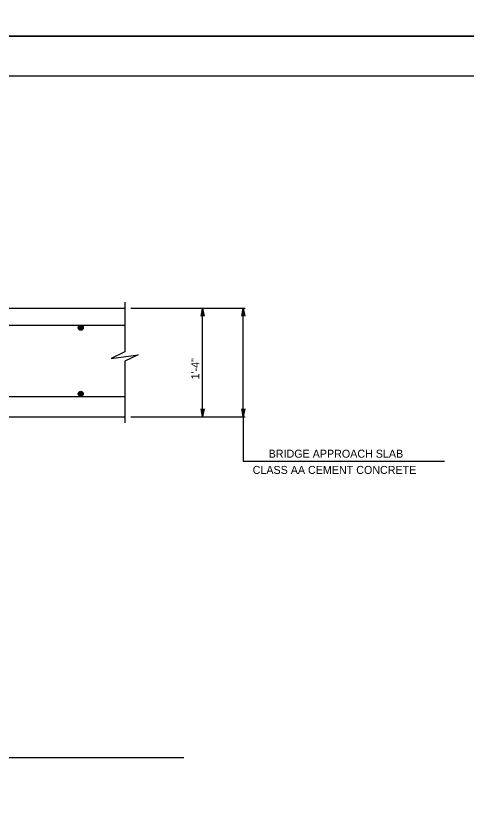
# Model space of a CAD drawing. Extents: x 636530 to 644067, y 294168 to 299122.
# Drawn here: x 639324.5 to 639493.4, y 296844.4 to 297146 of the extents above; entities that cross this region are included whole.
import ezdxf

# ---------------------------------------------------------------- set-up
doc = ezdxf.new("R2010")
doc.units = 0
doc.layers.add('1', color=7, linetype='Continuous')
doc.layers.add('PLT-BNDY', color=7, linetype='Continuous')

msp = doc.modelspace()

# ---------------------------------------------------------------- linework, layer by layer
at = {"layer": '1'}
for p, q in [((639832.78, 297123.48), (639046.78, 297123.48)), ((639217.03, 297036.51), (639365.32, 297036.51)), ((639365.32, 297038.81), (639365.32, 297020.15)), ((639367.53, 297036.51), (639410.31, 297036.51)), ((639394.39, 296995.87), (639394.39, 297036.51)), ((639409.63, 296995.87), (639409.63, 297036.51)), ((639314.79, 297030.16), (639365.32, 297030.16)), ((639365.32, 297016.63), (639365.32, 296993.56)), ((639314.79, 297003.49), (639365.32, 297003.49)), ((639215.69, 296995.87), (639365.32, 296995.87)), ((639367.53, 296995.87), (639410.31, 296995.87)), ((639409.63, 296995.87), (639409.63, 296979.14)), ((639409.63, 296979.14), (639485.02, 296979.14)), ((639093.54, 296868.17), (639387.37, 296868.17))]:
    msp.add_line(p, q, dxfattribs=at)
for points in [[(639394.39, 297036.51), (639394.95, 297033.52), (639394.79, 297033.75), (639394.59, 297033.87), (639394.39, 297033.91), (639394.19, 297033.87), (639393.99, 297033.75), (639393.83, 297033.52), (639394.39, 297036.51), (639393.99, 297033.75), (639394.19, 297033.87), (639394.39, 297036.51), (639394.39, 297033.91), (639394.59, 297033.87), (639394.39, 297036.51), (639394.79, 297033.75)], [(639409.63, 297036.51), (639410.19, 297033.52), (639410.03, 297033.75), (639409.83, 297033.87), (639409.63, 297033.91), (639409.43, 297033.87), (639409.23, 297033.75), (639409.07, 297033.52), (639409.63, 297036.51), (639409.23, 297033.75), (639409.43, 297033.87), (639409.63, 297036.51), (639409.63, 297033.91), (639409.83, 297033.87), (639409.63, 297036.51), (639410.03, 297033.75)], [(639365.32, 297020.15), (639360.13, 297017.61), (639370.28, 297018.99), (639365.32, 297016.63)], [(639394.39, 296995.87), (639393.83, 296998.85), (639393.99, 296998.62), (639394.19, 296998.5), (639394.39, 296998.47), (639394.59, 296998.5), (639394.79, 296998.62), (639394.95, 296998.85), (639394.39, 296995.87), (639394.79, 296998.62), (639394.59, 296998.5), (639394.39, 296995.87), (639394.39, 296998.47), (639394.19, 296998.5), (639394.39, 296995.87), (639393.99, 296998.62)], [(639409.63, 296995.87), (639409.07, 296998.85), (639409.23, 296998.62), (639409.43, 296998.5), (639409.63, 296998.47), (639409.83, 296998.5), (639410.03, 296998.62), (639410.19, 296998.85), (639409.63, 296995.87), (639410.03, 296998.62), (639409.83, 296998.5), (639409.63, 296995.87), (639409.63, 296998.47), (639409.43, 296998.5), (639409.63, 296995.87), (639409.23, 296998.62)]]:
    msp.add_lwpolyline(points, dxfattribs=at)
for centre, radius in [((639348.75, 297029.21), 0.952), ((639348.75, 297029.21), 0.714), ((639348.75, 297029.21), 0.476), ((639348.75, 297029.21), 0.238), ((639348.75, 297004.44), 0.952), ((639348.75, 297004.44), 0.714), ((639348.75, 297004.44), 0.476), ((639348.75, 297004.44), 0.238)]:
    msp.add_circle(centre, radius, dxfattribs=at)
at = {"layer": 'PLT-BNDY'}
for points in [[(639006.78, 297732.48), (639847.78, 297732.48), (639847.78, 297138.48), (639006.78, 297138.48)], [(639006.78, 297138.48), (639847.78, 297138.48), (639847.78, 296544.48), (639006.78, 296544.48)]]:
    msp.add_lwpolyline(points, close=True, dxfattribs=at)

# ---------------------------------------------------------------- texts
at = {"layer": '1'}
for s, rotation, p in [('1\'-4"', 90, (639393.13, 297009.85)), ('BRIDGE APPROACH SLAB', 360, (639419.13, 296980.5)), ('CLASS AA CEMENT CONCRETE', 360, (639413.14, 296974.42))]:
    msp.add_text(s, height=3, rotation=rotation, dxfattribs=at).set_placement(p)

doc.saveas('drawing.dxf')
